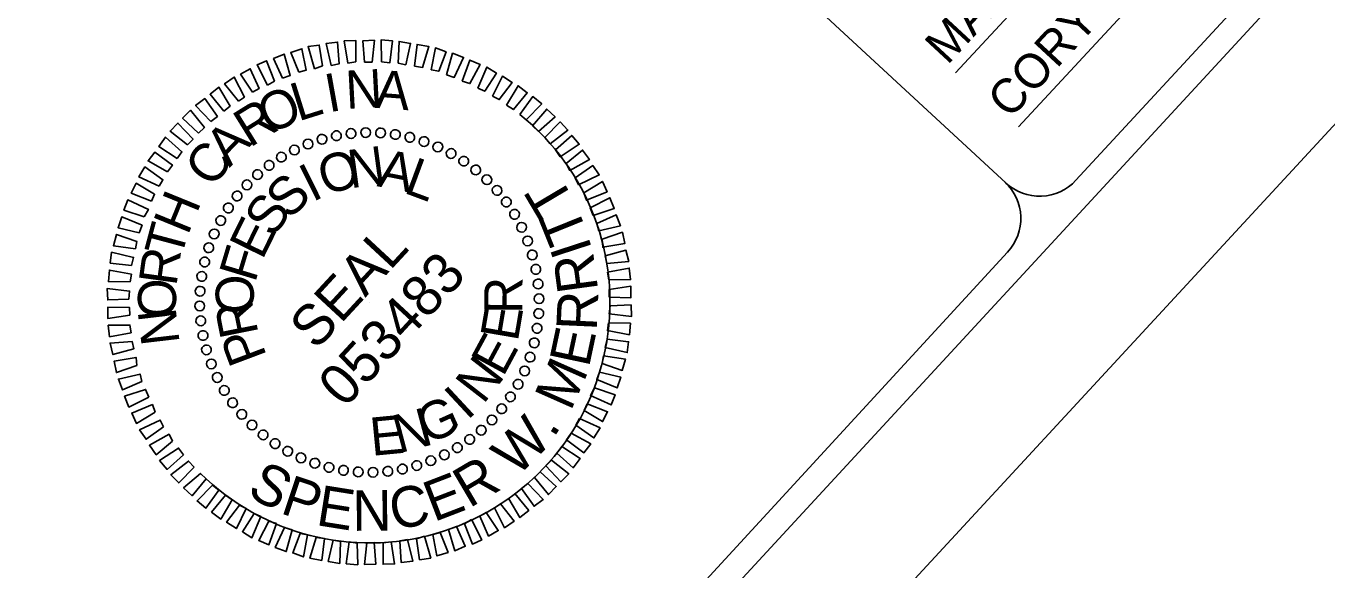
# Model space of a CAD drawing. Extents: x 1766669 to 1770980, y 998119 to 1002502.
# Drawn here: x 1770036 to 1770613, y 1000271 to 1000512 of the extents above; entities that cross this region are included whole.
import ezdxf

# ---------------------------------------------------------------- set-up
doc = ezdxf.new("R2010")
doc.units = 0
for name, color, linetype in [('Default Symbol CELL', 7, 'Continuous'), ('Exist DTM QL2 LIDAR Elevation Point', 7, 'Continuous'), ('Exist Guardrail', 7, 'Continuous'), ('PH Exist DTM Breakline', 7, 'Continuous')]:
    doc.layers.add(name, color=color, linetype=linetype)

msp = doc.modelspace()

# ---------------------------------------------------------------- linework, layer by layer
at = {"layer": 'Default Symbol CELL'}
for p, q in [((1768451.9, 998209.02), (1770874.08, 1000829.43)), ((1770502.06, 1000443.2), (1770858.62, 1000828.75)), ((1770471.1, 1000441.88), (1770212.92, 1000680.53)), ((1770448.63, 1000490.8), (1770587.08, 1000639.93)), ((1770476.55, 1000466.93), (1770615, 1000616.06))]:
    msp.add_line(p, q, dxfattribs=at)
msp.add_lwpolyline([(1770179.01, 1000093.5), (1770471.77, 1000411.36)], dxfattribs=at)
for centre, start, end in [((1770485.92, 1000458.11), 227.25123, 317.25123), ((1770455.64, 1000426.27), 317.25123, 47.25123)]:
    msp.add_arc(centre, 21.97, start, end, dxfattribs=at)
at = {"layer": 'Exist DTM QL2 LIDAR Elevation Point'}
msp.add_arc((1770188.83, 1000389.23), 106.61, 227.23314, 49.30605, dxfattribs=at)
at = {"layer": 'Exist Guardrail'}
for p, q in [((1770167.7, 1000461.56), (1770167.7, 1000461.56)), ((1770174.12, 1000462.97), (1770174.12, 1000462.97)), ((1770180.66, 1000464.08), (1770180.66, 1000464.08)), ((1770187.12, 1000464.43), (1770187.12, 1000464.43)), ((1770193.81, 1000464.37), (1770193.81, 1000464.37)), ((1770200.21, 1000463.56), (1770200.21, 1000463.56)), ((1770206.74, 1000462.22), (1770206.74, 1000462.22)), ((1770213.07, 1000460.45), (1770213.07, 1000460.45)), ((1770155.47, 1000456.73), (1770155.47, 1000456.73)), ((1770161.53, 1000459.3), (1770161.53, 1000459.3)), ((1770219.1, 1000458.14), (1770219.1, 1000458.14)), ((1770224.95, 1000455.18), (1770224.95, 1000455.18)), ((1770144.38, 1000449.83), (1770144.38, 1000449.83)), ((1770149.65, 1000453.53), (1770149.65, 1000453.53)), ((1770230.61, 1000451.58), (1770230.61, 1000451.58)), ((1770139.23, 1000445.81), (1770139.23, 1000445.81)), ((1770235.95, 1000447.86), (1770235.95, 1000447.86)), ((1770240.9, 1000443.49), (1770240.9, 1000443.49)), ((1770134.42, 1000441.27), (1770134.42, 1000441.27)), ((1770245.44, 1000438.67), (1770245.44, 1000438.67)), ((1770130.04, 1000436.32), (1770130.04, 1000436.32)), ((1770249.46, 1000433.52), (1770249.46, 1000433.52)), ((1770122.72, 1000425.32), (1770122.72, 1000425.32)), ((1770126.32, 1000430.97), (1770126.32, 1000430.97)), ((1770253.17, 1000428.25), (1770253.17, 1000428.25)), ((1770256.37, 1000422.43), (1770256.37, 1000422.43)), ((1770119.76, 1000419.47), (1770119.76, 1000419.47)), ((1770258.94, 1000416.38), (1770258.94, 1000416.38)), ((1770117.45, 1000413.44), (1770117.45, 1000413.44)), ((1770261.19, 1000410.2), (1770261.19, 1000410.2)), ((1770115.68, 1000407.1), (1770115.68, 1000407.1)), ((1770262.61, 1000403.78), (1770262.61, 1000403.78)), ((1770114.34, 1000400.58), (1770114.34, 1000400.58)), ((1770263.71, 1000397.24), (1770263.71, 1000397.24)), ((1770113.53, 1000394.18), (1770113.53, 1000394.18)), ((1770264.07, 1000390.78), (1770264.07, 1000390.78)), ((1770113.47, 1000387.49), (1770113.47, 1000387.49)), ((1770188.77, 1000389.13), (1770188.77, 1000389.13)), ((1770113.83, 1000381.03), (1770113.83, 1000381.03)), ((1770264.01, 1000384.09), (1770264.01, 1000384.09)), ((1770114.93, 1000374.49), (1770114.93, 1000374.49)), ((1770263.2, 1000377.69), (1770263.2, 1000377.69)), ((1770116.35, 1000368.07), (1770116.35, 1000368.07)), ((1770261.86, 1000371.16), (1770261.86, 1000371.16)), ((1770118.6, 1000361.89), (1770118.6, 1000361.89)), ((1770260.09, 1000364.83), (1770260.09, 1000364.83)), ((1770257.77, 1000358.8), (1770257.77, 1000358.8)), ((1770121.17, 1000355.84), (1770121.17, 1000355.84)), ((1770254.81, 1000352.95), (1770254.81, 1000352.95)), ((1770124.37, 1000350.02), (1770124.37, 1000350.02)), ((1770128.08, 1000344.75), (1770128.08, 1000344.75)), ((1770251.21, 1000347.29), (1770251.21, 1000347.29)), ((1770132.1, 1000339.59), (1770132.1, 1000339.59)), ((1770247.49, 1000341.95), (1770247.49, 1000341.95)), ((1770136.64, 1000334.78), (1770136.64, 1000334.78)), ((1770243.12, 1000337), (1770243.12, 1000337)), ((1770141.58, 1000330.41), (1770141.58, 1000330.41)), ((1770233.16, 1000328.44), (1770233.16, 1000328.44)), ((1770238.31, 1000332.46), (1770238.31, 1000332.46)), ((1770146.93, 1000326.69), (1770146.93, 1000326.69)), ((1770152.59, 1000323.09), (1770152.59, 1000323.09)), ((1770222.07, 1000321.54), (1770222.07, 1000321.54)), ((1770227.89, 1000324.74), (1770227.89, 1000324.74)), ((1770158.43, 1000320.13), (1770158.43, 1000320.13)), ((1770164.47, 1000317.82), (1770164.47, 1000317.82)), ((1770170.8, 1000316.05), (1770170.8, 1000316.05)), ((1770209.84, 1000316.71), (1770209.84, 1000316.71)), ((1770216.01, 1000318.97), (1770216.01, 1000318.97)), ((1770177.33, 1000314.71), (1770177.33, 1000314.71)), ((1770183.73, 1000313.89), (1770183.73, 1000313.89)), ((1770190.42, 1000313.83), (1770190.42, 1000313.83)), ((1770196.88, 1000314.19), (1770196.88, 1000314.19)), ((1770203.42, 1000315.29), (1770203.42, 1000315.29))]:
    msp.add_line(p, q, dxfattribs=at)
for points in [[(1770157.43, 1000491.09), (1770153.9, 1000499.87), (1770158.83, 1000501.44), (1770160.68, 1000491.96)], [(1770164.37, 1000492.64), (1770161.55, 1000502.4), (1770166.51, 1000503.12), (1770167.94, 1000493.84)], [(1770171.85, 1000494.09), (1770169.57, 1000503.77), (1770174.64, 1000504.39), (1770175.33, 1000494.76)], [(1770179.14, 1000495.12), (1770177.59, 1000504.93), (1770182.68, 1000505.13), (1770182.73, 1000495.68)], [(1770186.66, 1000495.52), (1770185.87, 1000505.04), (1770190.95, 1000505.24), (1770189.95, 1000495.54)], [(1770194.19, 1000495.7), (1770193.92, 1000505.35), (1770199.03, 1000504.91), (1770197.82, 1000495.21)], [(1770201.54, 1000495.03), (1770201.91, 1000504.71), (1770207.03, 1000503.84), (1770204.85, 1000494.42)], [(1770208.7, 1000493.72), (1770209.92, 1000503.42), (1770215.16, 1000502.46), (1770212.33, 1000493.22)], [(1770216.19, 1000492.1), (1770218.05, 1000501.83), (1770222.78, 1000500.1), (1770219.51, 1000491.48)], [(1770143.53, 1000485.35), (1770138.94, 1000494.3), (1770143.11, 1000496.16), (1770146.65, 1000487.17)], [(1770150.21, 1000488.37), (1770146.26, 1000497.13), (1770150.96, 1000499.12), (1770153.66, 1000489.67)], [(1770222.97, 1000489.92), (1770225.67, 1000499.47), (1770230.52, 1000497.64), (1770226.41, 1000488.78)], [(1770229.97, 1000487.11), (1770233.33, 1000496.48), (1770237.86, 1000494.53), (1770233.3, 1000486.07)], [(1770130.65, 1000478.27), (1770124.51, 1000485.99), (1770128.85, 1000488.92), (1770133.34, 1000480.07)], [(1770136.97, 1000482.23), (1770131.67, 1000490.2), (1770135.93, 1000492.59), (1770139.88, 1000483.83)], [(1770236.89, 1000483.98), (1770240.88, 1000493.37), (1770245.12, 1000490.67), (1770239.91, 1000482.62)], [(1770243.4, 1000480.42), (1770247.72, 1000489.29), (1770252.08, 1000486.48), (1770246.32, 1000478.94)], [(1770124.24, 1000473.78), (1770118.11, 1000481.29), (1770122.02, 1000484.41), (1770127.01, 1000476.11)], [(1770249.6, 1000476.52), (1770254.68, 1000485.1), (1770258.73, 1000481.97), (1770252.65, 1000474.51)], [(1770118.47, 1000469.31), (1770111.72, 1000476.37), (1770115.74, 1000479.39), (1770121.35, 1000471.54)], [(1770255.49, 1000472.29), (1770261.23, 1000480.26), (1770265.18, 1000477.01), (1770258.34, 1000470.06)], [(1770113.04, 1000464.11), (1770105.89, 1000470.73), (1770109.36, 1000474.26), (1770115.6, 1000466.65)], [(1770261.1, 1000467.3), (1770267.39, 1000474.77), (1770271.13, 1000471.3), (1770263.74, 1000464.86)], [(1770108.04, 1000458.93), (1770100.38, 1000465), (1770103.85, 1000468.53), (1770110.6, 1000461.47)], [(1770266.5, 1000462.1), (1770273.35, 1000469.05), (1770276.77, 1000465.47), (1770268.94, 1000459.43)], [(1770103.5, 1000452.91), (1770095.33, 1000458.22), (1770098.36, 1000462.37), (1770105.62, 1000455.86)], [(1770271.28, 1000456.66), (1770278.46, 1000463.09), (1770281.79, 1000459.19), (1770273.41, 1000453.66)], [(1770099.27, 1000447.01), (1770090.6, 1000451.77), (1770093.63, 1000455.71), (1770101.39, 1000449.96)], [(1770276.08, 1000450.58), (1770283.28, 1000456.59), (1770286.31, 1000452.36), (1770277.58, 1000447.56)], [(1770095.59, 1000440.61), (1770086.52, 1000444.72), (1770089.21, 1000449.17), (1770097.18, 1000443.43)], [(1770280.04, 1000444.26), (1770287.79, 1000449.76), (1770290.71, 1000445.63), (1770281.54, 1000441.24)], [(1770283.8, 1000437.72), (1770292.09, 1000442.71), (1770294.18, 1000438.12), (1770284.99, 1000434.37)], [(1770092.13, 1000434), (1770083.19, 1000437.58), (1770085.35, 1000441.91), (1770093.5, 1000437.03)], [(1770088.9, 1000426.98), (1770079.87, 1000430.02), (1770081.6, 1000434.55), (1770090.79, 1000430.34)], [(1770286.6, 1000431.04), (1770295.45, 1000435.52), (1770297.34, 1000430.71), (1770288.01, 1000427.69)], [(1770086.73, 1000419.99), (1770077.31, 1000422.17), (1770078.92, 1000427.01), (1770087.98, 1000423.33)], [(1770289.63, 1000424.15), (1770298.19, 1000427.88), (1770300.07, 1000423.07), (1770290.5, 1000420.89)], [(1770291.92, 1000417.12), (1770300.93, 1000420.23), (1770301.97, 1000415.18), (1770292.27, 1000413.53)], [(1770084.99, 1000412.81), (1770075.28, 1000414.24), (1770076.68, 1000419.28), (1770085.61, 1000416.13)], [(1770083.26, 1000405.42), (1770073.88, 1000406.54), (1770074.44, 1000411.34), (1770084.18, 1000409.07)], [(1770293.27, 1000409.75), (1770302.51, 1000412.23), (1770303.77, 1000407.18), (1770294.03, 1000406.38)], [(1770082.7, 1000398.18), (1770073.03, 1000398.34), (1770073.47, 1000403.45), (1770083.2, 1000401.6)], [(1770294.39, 1000402.57), (1770303.98, 1000404.32), (1770304.61, 1000399.25), (1770294.95, 1000399.2)], [(1770082.03, 1000390.62), (1770072.71, 1000390.26), (1770072.51, 1000395.35), (1770082.43, 1000394.14)], [(1770295.01, 1000394.85), (1770304.72, 1000396.29), (1770304.71, 1000391.19), (1770295.14, 1000391.46)], [(1770082.53, 1000383.42), (1770072.82, 1000381.98), (1770072.83, 1000387.08), (1770082.39, 1000386.81)], [(1770295.5, 1000387.65), (1770304.83, 1000388.01), (1770305.03, 1000382.92), (1770295.11, 1000384.13)], [(1770294.84, 1000380.09), (1770304.51, 1000379.93), (1770304.07, 1000374.82), (1770294.34, 1000376.67)], [(1770083.14, 1000375.7), (1770073.55, 1000373.94), (1770072.93, 1000379.02), (1770082.59, 1000379.07)], [(1770084.27, 1000368.52), (1770075.03, 1000366.04), (1770073.77, 1000371.09), (1770083.5, 1000371.89)], [(1770294.27, 1000372.85), (1770303.66, 1000371.72), (1770303.1, 1000366.93), (1770293.35, 1000369.2)], [(1770085.62, 1000361.14), (1770076.61, 1000358.03), (1770075.57, 1000363.09), (1770085.27, 1000364.74)], [(1770292.54, 1000365.46), (1770302.26, 1000364.03), (1770300.86, 1000358.98), (1770291.93, 1000362.14)], [(1770087.91, 1000354.12), (1770079.35, 1000350.39), (1770077.46, 1000355.2), (1770087.04, 1000357.38)], [(1770290.8, 1000358.28), (1770300.23, 1000356.09), (1770298.61, 1000351.26), (1770289.55, 1000354.94)], [(1770090.94, 1000347.23), (1770082.09, 1000342.75), (1770080.2, 1000347.56), (1770089.53, 1000350.58)], [(1770288.63, 1000351.29), (1770297.67, 1000348.25), (1770295.93, 1000343.72), (1770286.75, 1000347.93)], [(1770093.74, 1000340.55), (1770085.44, 1000335.56), (1770083.36, 1000340.15), (1770092.55, 1000343.9)], [(1770285.4, 1000344.27), (1770294.35, 1000340.69), (1770292.19, 1000336.36), (1770284.03, 1000341.24)], [(1770097.5, 1000334.01), (1770089.75, 1000328.51), (1770086.83, 1000332.64), (1770096, 1000337.03)], [(1770281.94, 1000337.66), (1770291.02, 1000333.55), (1770288.33, 1000329.1), (1770280.36, 1000334.84)], [(1770101.46, 1000327.69), (1770094.26, 1000321.67), (1770091.23, 1000325.91), (1770099.96, 1000330.71)], [(1770278.27, 1000331.25), (1770286.94, 1000326.5), (1770283.91, 1000322.56), (1770276.15, 1000328.31)], [(1770106.26, 1000321.61), (1770099.08, 1000315.17), (1770095.74, 1000319.08), (1770104.13, 1000324.6)], [(1770274.04, 1000325.36), (1770282.2, 1000320.05), (1770279.18, 1000315.9), (1770271.92, 1000322.41)], [(1770111.03, 1000316.17), (1770104.19, 1000309.22), (1770100.76, 1000312.8), (1770108.6, 1000318.83)], [(1770269.49, 1000319.34), (1770277.16, 1000313.27), (1770273.69, 1000309.74), (1770266.94, 1000316.8)], [(1770116.44, 1000310.97), (1770110.15, 1000303.5), (1770106.4, 1000306.97), (1770113.8, 1000313.41)], [(1770264.49, 1000314.16), (1770271.65, 1000307.54), (1770268.18, 1000304.01), (1770261.94, 1000311.62)], [(1770122.04, 1000305.98), (1770116.3, 1000298.01), (1770112.36, 1000301.25), (1770119.2, 1000308.21)], [(1770253.3, 1000304.49), (1770259.43, 1000296.98), (1770255.52, 1000293.86), (1770250.52, 1000302.15)], [(1770259.07, 1000308.96), (1770265.82, 1000301.9), (1770261.8, 1000298.88), (1770256.18, 1000306.73)], [(1770127.94, 1000301.75), (1770122.86, 1000293.17), (1770118.81, 1000296.3), (1770124.89, 1000303.76)], [(1770134.14, 1000297.85), (1770129.82, 1000288.98), (1770125.46, 1000291.78), (1770131.22, 1000299.33)], [(1770246.89, 1000300), (1770253.03, 1000292.27), (1770248.68, 1000289.35), (1770244.2, 1000298.19)], [(1770140.65, 1000294.28), (1770136.66, 1000284.89), (1770132.42, 1000287.6), (1770137.62, 1000295.65)], [(1770234, 1000292.92), (1770238.6, 1000283.97), (1770234.42, 1000282.11), (1770230.89, 1000291.1)], [(1770240.57, 1000296.04), (1770245.87, 1000288.07), (1770241.61, 1000285.68), (1770237.66, 1000294.44)], [(1770147.56, 1000291.16), (1770144.21, 1000281.79), (1770139.68, 1000283.74), (1770144.23, 1000292.19)], [(1770154.57, 1000288.35), (1770151.86, 1000278.8), (1770147.02, 1000280.63), (1770151.13, 1000289.49)], [(1770220.11, 1000287.18), (1770223.63, 1000278.4), (1770218.71, 1000276.83), (1770216.85, 1000286.31)], [(1770227.33, 1000289.9), (1770231.28, 1000281.13), (1770226.58, 1000279.15), (1770223.88, 1000288.6)], [(1770161.34, 1000286.17), (1770159.49, 1000276.44), (1770154.75, 1000278.17), (1770158.03, 1000286.78)], [(1770168.84, 1000284.55), (1770167.62, 1000274.84), (1770162.38, 1000275.81), (1770165.21, 1000285.05)], [(1770176, 1000283.24), (1770175.63, 1000273.56), (1770170.5, 1000274.43), (1770172.68, 1000283.85)], [(1770183.35, 1000282.57), (1770183.62, 1000272.92), (1770178.51, 1000273.36), (1770179.72, 1000283.06)], [(1770190.88, 1000282.75), (1770191.67, 1000273.23), (1770186.59, 1000273.03), (1770187.59, 1000282.73)], [(1770198.4, 1000283.15), (1770199.95, 1000273.34), (1770194.86, 1000273.14), (1770194.81, 1000282.59)], [(1770205.68, 1000284.18), (1770207.97, 1000274.5), (1770202.9, 1000273.88), (1770202.21, 1000283.51)], [(1770213.16, 1000285.63), (1770215.98, 1000275.87), (1770211.02, 1000275.15), (1770209.6, 1000284.43)]]:
    msp.add_lwpolyline(points, close=True, dxfattribs=at)
for centre, major_axis in [((1770180.61, 1000463.93), (-0.23, 2.15)), ((1770187.16, 1000464.36), (-0.05, 2.16)), ((1770193.73, 1000464.21), (0.14, 2.16)), ((1770200.25, 1000463.49), (0.33, 2.13)), ((1770161.53, 1000459.27), (-0.78, 2.01)), ((1770167.75, 1000461.38), (-0.6, 2.07)), ((1770174.13, 1000462.94), (-0.42, 2.12)), ((1770206.69, 1000462.21), (0.51, 2.1)), ((1770212.99, 1000460.37), (0.7, 2.05)), ((1770219.11, 1000457.99), (0.87, 1.98)), ((1770149.77, 1000453.48), (-1.12, 1.85)), ((1770155.52, 1000456.63), (-0.95, 1.94)), ((1770224.99, 1000455.08), (1.04, 1.89)), ((1770230.6, 1000451.67), (1.2, 1.8)), ((1770144.31, 1000449.83), (-1.28, 1.74)), ((1770235.89, 1000447.79), (1.35, 1.68)), ((1770134.44, 1000441.19), (-1.56, 1.49)), ((1770139.19, 1000445.73), (-1.42, 1.62)), ((1770240.83, 1000443.46), (1.49, 1.56)), ((1770130.11, 1000436.26), (-1.68, 1.35)), ((1770245.36, 1000438.72), (1.62, 1.42)), ((1770126.23, 1000430.97), (-1.8, 1.2)), ((1770249.47, 1000433.59), (1.74, 1.28)), ((1770122.82, 1000425.36), (-1.89, 1.04)), ((1770253.11, 1000428.13), (1.85, 1.12)), ((1770119.92, 1000419.47), (-1.98, 0.87)), ((1770256.27, 1000422.38), (1.94, 0.95)), ((1770117.53, 1000413.35), (-2.05, 0.7)), ((1770258.91, 1000416.37), (2.01, 0.78)), ((1770115.69, 1000407.05), (-2.1, 0.51)), ((1770261.01, 1000410.15), (2.07, 0.6)), ((1770114.41, 1000400.62), (-2.13, 0.33)), ((1770262.57, 1000403.78), (2.12, 0.42)), ((1770263.57, 1000397.29), (2.15, 0.23)), ((1770113.69, 1000394.09), (-2.16, 0.14)), ((1770263.99, 1000390.74), (2.16, 0.05)), ((1770113.55, 1000387.53), (-2.16, -0.05)), ((1770263.85, 1000384.18), (2.16, -0.14)), ((1770113.97, 1000380.98), (-2.15, -0.23)), ((1770263.13, 1000377.65), (2.13, -0.33)), ((1770114.97, 1000374.49), (-2.12, -0.42)), ((1770261.84, 1000371.21), (2.1, -0.51)), ((1770116.52, 1000368.12), (-2.07, -0.6)), ((1770118.63, 1000361.9), (-2.01, -0.78)), ((1770260, 1000364.91), (2.05, -0.7)), ((1770121.27, 1000355.89), (-1.94, -0.95)), ((1770257.62, 1000358.8), (1.98, -0.87)), ((1770124.43, 1000350.13), (-1.85, -1.12)), ((1770254.72, 1000352.91), (1.89, -1.04)), ((1770128.07, 1000344.67), (-1.74, -1.28)), ((1770251.31, 1000347.3), (1.8, -1.2)), ((1770132.18, 1000339.55), (-1.62, -1.42)), ((1770243.09, 1000337.08), (1.56, -1.49)), ((1770247.42, 1000342.01), (1.68, -1.35)), ((1770136.71, 1000334.81), (-1.49, -1.56)), ((1770238.35, 1000332.54), (1.42, -1.62)), ((1770141.64, 1000330.48), (-1.35, -1.68)), ((1770146.94, 1000326.6), (-1.2, -1.8)), ((1770227.77, 1000324.79), (1.12, -1.85)), ((1770233.23, 1000328.44), (1.28, -1.74)), ((1770152.55, 1000323.19), (-1.04, -1.89)), ((1770158.43, 1000320.28), (-0.87, -1.98)), ((1770222.01, 1000321.64), (0.95, -1.94)), ((1770164.55, 1000317.9), (-0.7, -2.05)), ((1770170.85, 1000316.06), (-0.51, -2.1)), ((1770177.29, 1000314.78), (-0.33, -2.13)), ((1770183.81, 1000314.06), (-0.14, -2.16)), ((1770190.37, 1000313.91), (0.05, -2.16)), ((1770196.92, 1000314.34), (0.23, -2.15)), ((1770203.41, 1000315.33), (0.42, -2.12)), ((1770209.79, 1000316.89), (0.6, -2.07)), ((1770216, 1000319), (0.78, -2.01))]:
    msp.add_ellipse(centre, major_axis=major_axis, ratio=0.999708, dxfattribs=at)
at = {"layer": 'PH Exist DTM Breakline'}
msp.add_lwpolyline([(1766668.62, 999760.16), (1769205.64, 1002501.94), (1770979.75, 1000860.32), (1768442.74, 998118.54)], close=True, dxfattribs=at)

# ---------------------------------------------------------------- texts
at = {"layer": 'Default Symbol CELL'}
for s, p in [('MARK COLE', (1770445.08, 1000493.94)), ('CORY WOOD', (1770472.79, 1000469.96))]:
    msp.add_text(s, height=15.24, rotation=47.237, dxfattribs=at).set_placement(p)
at = {"layer": 'Exist Guardrail'}
for s, height, rotation, p in [('I', 16.91, 10.24151, (1770170.75, 1000473.25)), ('N', 16.92, 3.04028, (1770178.55, 1000474.82)), ('A', 16.92, 355.83852, (1770191.05, 1000475.31)), ('O', 16.91, 24.64254, (1770144.18, 1000463.3)), ('L', 16.91, 17.44225, (1770157.22, 1000469.22)), ('R', 16.91, 31.84247, (1770135.7, 1000457.45)), ('A', 16.91, 46.24169, (1770126.7, 1000448.61)), ('C', 16.91, 53.44124, (1770119.31, 1000439.3)), ('O', 16.91, 17.05485, (1770169.1, 1000436.35)), ('N', 16.92, 7.69798, (1770180.33, 1000439.65)), ('A', 16.92, 348.98164, (1770191.87, 1000440.63)), ('I', 16.91, 26.41097, (1770163.49, 1000433.37)), ('L', 16.92, 339.62222, (1770203.44, 1000437.89)), ('S', 16.91, 45.12177, (1770153.19, 1000425.33)), ('H', 16.91, 67.84085, (1770108.23, 1000418.49)), ('S', 16.91, 54.47698, (1770145.96, 1000417.3)), ('T', 17.99, 120.69214, (1770280.14, 1000433.68)), ('E', 16.91, 63.83244, (1770141.24, 1000407.56)), ('T', 17.99, 111.994, (1770285.82, 1000419.36)), ('T', 16.91, 75.04114, (1770105.24, 1000407.97)), ('F', 16.91, 73.1884, (1770138.03, 1000397.46)), ('SEAL', 17.995, 47.22137, (1770165.12, 1000367.57)), ('I', 17.99, 108.04101, (1770287.66, 1000412.6)), ('R', 16.92, 82.24188, (1770103.16, 1000396)), ('053483', 17.995, 47.22137, (1770177.83, 1000341.93)), ('R', 17.99, 97.75858, (1770290.25, 1000394.58)), ('O', 16.92, 89.44311, (1770102.96, 1000382.09)), ('O', 16.92, 91.90261, (1770137.8, 1000384.19)), ('R', 16.92, 89.70278, (1770256.58, 1000384.02)), ('R', 17.99, 87.47614, (1770289.57, 1000376.39)), ('N', 16.92, 96.64487, (1770104.66, 1000371.12)), ('R', 16.92, 101.26102, (1770139.63, 1000375.34)), ('E', 16.92, 80.34546, (1770254.52, 1000371.41)), ('P', 16.92, 110.62026, (1770143.41, 1000365.3)), ('E', 16.91, 61.63313, (1770248.02, 1000355.77)), ('E', 17.99, 77.97809, (1770286.07, 1000359.94)), ('N', 16.91, 52.27776, (1770239.25, 1000343.65)), ('M', 17.99, 66.11912, (1770277.98, 1000340.58)), ('I', 16.91, 42.92257, (1770232.1, 1000336.57)), ('G', 16.91, 24.21161, (1770214.57, 1000326.02)), ('E', 16.91, 5.49826, (1770189.81, 1000321.14)), ('N', 16.92, 14.85533, (1770201.87, 1000322.24)), ('W', 17.99, 44.77763, (1770254.16, 1000311.48)), ('.', 17.99, 58.21314, (1770270.44, 1000328.78)), ('S', 17.99, 331.98513, (1770133.88, 1000303.82)), ('R', 17.99, 30.5422, (1770233.04, 1000297.8)), ('P', 17.99, 341.48318, (1770148.73, 1000295.92)), ('E', 17.99, 21.04415, (1770217.34, 1000291.76)), ('E', 17.99, 350.98123, (1770164.68, 1000290.58)), ('N', 17.99, 0.47928, (1770181.29, 1000287.95)), ('C', 17.99, 10.76172, (1770199.48, 1000288.23))]:
    msp.add_text(s, height=height, rotation=rotation, dxfattribs=at).set_placement(p)

doc.saveas('drawing.dxf')
